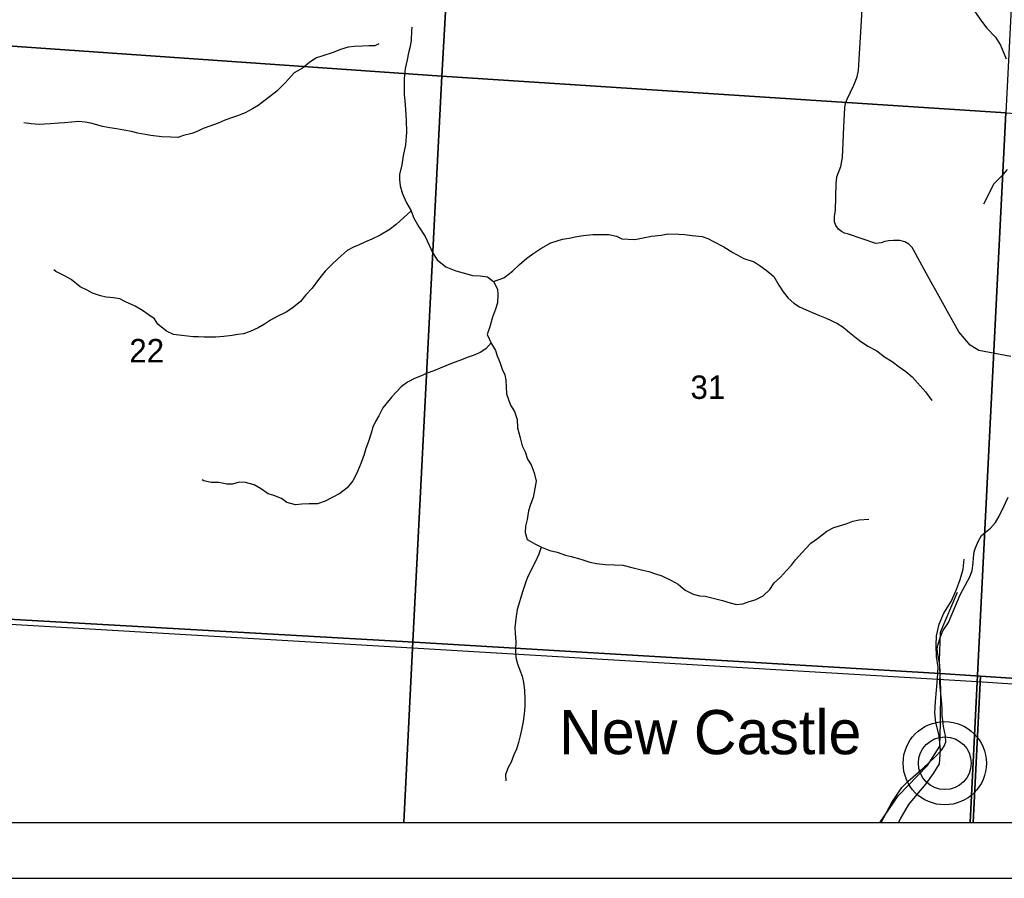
# Model space of a CAD drawing. Extents: x 0 to 44, y -23.8 to 22.
# Drawn here: x 5.562 to 7.321, y 14 to 15.535 of the extents above; entities that cross this region are included whole.
import ezdxf

# ---------------------------------------------------------------- set-up
doc = ezdxf.new("R2010")
doc.units = 0
for name, color, linetype in [('Default', 7, 'Continuous'), ('GM_X_Minor_River', 7, 'Continuous'), ('GM_X_Rail_Line', 7, 'Continuous'), ('GM_X_Section', 7, 'Continuous'), ('GM_X_Section_Text', 7, 'Continuous'), ('GM_X_State_Route', 7, 'Continuous'), ('GM_X_Unincorporated', 7, 'Continuous'), ('GM_X_Unincorporated_Location', 7, 'Continuous'), ('GM_X_Unincorporated_Text', 7, 'Continuous'), ('SH_Cut_Line', 7, 'Continuous'), ('SH_Data', 7, 'Continuous')]:
    doc.layers.add(name, color=color, linetype=linetype)

msp = doc.modelspace()

# ---------------------------------------------------------------- linework, layer by layer
at = {"layer": 'Default'}
msp.add_lwpolyline([(4.1422, 16.6361), (4.3476, 16.1408), (4.5387, 15.7097), (4.856, 14.9939), (4.4538, 14.8144), (4.3443, 14.7655), (3.8639, 14.5533), (4.2071, 14.5278), (4.3437, 14.5311), (4.4919, 14.5227), (6.267, 14.4223), (7.2065, 14.3659), (7.2787, 14.3616), (7.5613, 14.343)], dxfattribs=at)
for points in [[(2.838, 14.1), (7.2659, 14.1), (7.2787, 14.3616), (7.2065, 14.3659), (6.267, 14.4223), (4.4919, 14.5227), (4.3437, 14.5311), (4.2071, 14.5278), (3.8639, 14.5533), (3.0317, 14.1856)], [(5.2407, 14.1), (6.2484, 14.1), (6.2643, 14.4116), (5.2616, 14.4705)], [(6.2484, 14.1), (7.2605, 14.1), (7.2726, 14.3512), (6.2643, 14.4116)], [(7.2659, 14.1), (8.9, 14.1), (8.9, 14.2547), (8.4778, 14.2825), (8.045, 14.3111), (7.5613, 14.343), (7.2787, 14.3616)], [(7.2605, 14.1), (8.2666, 14.1), (8.2829, 14.2852), (7.2726, 14.3512)]]:
    msp.add_lwpolyline(points, close=True, dxfattribs=at)
at = {"layer": 'GM_X_Minor_River'}
for points in [[(7.2686, 15.5494), (7.2791, 15.5343), (7.2901, 15.5195), (7.3056, 15.5036), (7.3147, 15.4891), (7.3249, 15.4649)], [(6.2627, 15.5213), (6.2623, 15.5148), (6.2615, 15.4981), (6.2596, 15.4871), (6.2566, 15.4753), (6.2543, 15.4628), (6.2509, 15.4473), (6.2494, 15.4294), (6.249, 15.4173), (6.2494, 15.4006), (6.2502, 15.3896), (6.2513, 15.3741), (6.2528, 15.3547), (6.2536, 15.3335), (6.2517, 15.3111), (6.2475, 15.2914), (6.2449, 15.2755), (6.2407, 15.258), (6.2407, 15.2485), (6.2418, 15.2379), (6.246, 15.2235), (6.2535, 15.2076), (6.2615, 15.1928), (6.266, 15.181), (6.2755, 15.1647), (6.2864, 15.1469), (6.2936, 15.1317), (6.2996, 15.1185), (6.3083, 15.1052), (6.3234, 15.0927), (6.3412, 15.0859), (6.3609, 15.0806), (6.3711, 15.0772), (6.3851, 15.0768), (6.3983, 15.0753), (6.4089, 15.0669), (6.4157, 15.0533), (6.4164, 15.0434), (6.4157, 15.0286), (6.4123, 15.0173), (6.407, 15.0029), (6.4017, 14.9839), (6.3975, 14.9721), (6.4054, 14.9554), (6.4122, 14.9433), (6.4153, 14.9338), (6.4202, 14.9228), (6.4243, 14.9099), (6.4289, 14.9001), (6.4308, 14.8902), (6.4311, 14.8785), (6.4319, 14.866), (6.4353, 14.8561), (6.4394, 14.8455), (6.4462, 14.8341), (6.4508, 14.8201), (6.4519, 14.8053), (6.4561, 14.7875), (6.4598, 14.7731), (6.4655, 14.7624), (6.4693, 14.7492), (6.4761, 14.7393), (6.4814, 14.7245), (6.4852, 14.7101), (6.4817, 14.69), (6.4795, 14.6805), (6.4749, 14.6684), (6.4715, 14.657), (6.4689, 14.6411), (6.4659, 14.6297), (6.4655, 14.6179), (6.4689, 14.6058), (6.484, 14.5975), (6.4946, 14.5918), (6.5093, 14.5861), (6.5222, 14.5827), (6.5373, 14.5778), (6.5475, 14.5751), (6.5645, 14.5702), (6.5808, 14.5649), (6.5936, 14.5626), (6.608, 14.5611), (6.6246, 14.5604), (6.6397, 14.5596), (6.656, 14.5558), (6.6756, 14.5509), (6.6862, 14.5486), (6.6979, 14.5445), (6.7097, 14.5407), (6.7255, 14.5331), (6.7388, 14.5255), (6.7512, 14.5153), (6.7656, 14.5081), (6.7769, 14.5051), (6.7871, 14.5043), (6.8011, 14.5009), (6.8178, 14.4964), (6.8314, 14.4926), (6.8431, 14.4892), (6.8544, 14.4907)], [(6.2037, 15.4916), (6.1969, 15.4882), (6.1863, 15.4878), (6.175, 15.4874), (6.1606, 15.4866), (6.1493, 15.4855), (6.1357, 15.4813), (6.1224, 15.476), (6.1039, 15.4699), (6.0926, 15.4665), (6.0805, 15.4589), (6.0676, 15.4483), (6.0525, 15.44), (6.037, 15.4225), (6.0215, 15.4069), (6.0086, 15.3967), (5.9882, 15.3815), (5.9784, 15.3751), (5.9648, 15.3682), (5.9512, 15.3629), (5.9391, 15.3587), (5.9274, 15.3546), (5.9168, 15.3496), (5.9017, 15.3447), (5.8903, 15.3401), (5.8805, 15.3356), (5.8699, 15.3314), (5.8552, 15.328), (5.8446, 15.3242), (5.8325, 15.3246), (5.8162, 15.3253), (5.7966, 15.328), (5.7867, 15.3298), (5.7735, 15.3321), (5.7618, 15.3348), (5.7486, 15.3374), (5.7353, 15.3397), (5.7232, 15.3412), (5.7104, 15.3438), (5.7002, 15.3469), (5.6896, 15.3495), (5.6794, 15.3514), (5.6681, 15.3525), (5.6548, 15.3514), (5.6423, 15.3506), (5.6321, 15.3495), (5.617, 15.3483), (5.6068, 15.348), (5.597, 15.3476), (5.583, 15.3483), (5.5698, 15.3506)], [(7.3263, 15.2669), (7.3165, 15.2551), (7.3029, 15.2415), (7.284, 15.2052)], [(6.2615, 15.1928), (6.235, 15.1685), (6.2225, 15.1594), (6.2063, 15.1495), (6.1912, 15.1423), (6.1798, 15.1378), (6.1689, 15.1324), (6.1586, 15.1279), (6.1473, 15.1222), (6.1367, 15.1127), (6.122, 15.0987), (6.108, 15.0854), (6.0959, 15.0702), (6.0845, 15.055), (6.0732, 15.0429), (6.0637, 15.0311), (6.0486, 15.0186), (6.0384, 15.0118), (6.0222, 15.0042), (6.0104, 14.9974), (5.9995, 14.9905), (5.9881, 14.9837), (5.9738, 14.9776), (5.9624, 14.9734), (5.9518, 14.9723), (5.942, 14.9704), (5.9269, 14.9685), (5.9125, 14.9674), (5.9027, 14.967), (5.8917, 14.9673), (5.8819, 14.9681), (5.8721, 14.9677), (5.8517, 14.97), (5.8373, 14.9722), (5.8248, 14.9779), (5.8093, 14.9904), (5.8033, 15.0003), (5.792, 15.0079), (5.7818, 15.0151), (5.7685, 15.0227), (5.7511, 15.0302), (5.7413, 15.0355), (5.73, 15.0374), (5.7167, 15.0386), (5.7069, 15.0412), (5.6926, 15.0458), (5.6827, 15.0514), (5.6703, 15.0571), (5.6544, 15.0704), (5.6434, 15.0764), (5.6268, 15.0844), (5.623, 15.0878)], [(6.4089, 15.0669), (6.427, 15.0734), (6.4425, 15.0852), (6.4554, 15.0973), (6.4686, 15.1083), (6.4811, 15.1174), (6.4936, 15.1258), (6.5113, 15.136), (6.5321, 15.1425), (6.5438, 15.144), (6.5578, 15.147), (6.5695, 15.1489), (6.5862, 15.1505), (6.6149, 15.1505), (6.6285, 15.1475), (6.6383, 15.1429), (6.6614, 15.1418), (6.6731, 15.1441), (6.6909, 15.1479), (6.7083, 15.1498), (6.7204, 15.1517), (6.7396, 15.1513), (6.7502, 15.1505), (6.7635, 15.149), (6.7816, 15.1472), (6.7918, 15.1434), (6.8016, 15.1381), (6.8205, 15.129), (6.8364, 15.1184), (6.8557, 15.1081), (6.8746, 15.1017), (6.8852, 15.0945), (6.8961, 15.0869), (6.9093, 15.0755), (6.9188, 15.06), (6.9264, 15.0482), (6.935, 15.0369), (6.9452, 15.0278), (6.9555, 15.0217), (6.9728, 15.0138), (6.9883, 15.0073), (7.0031, 15.0013), (7.0224, 14.9925), (7.0337, 14.9853), (7.0447, 14.9755), (7.0628, 14.9615), (7.0775, 14.9512), (7.0938, 14.9429), (7.1074, 14.9323), (7.121, 14.9236), (7.1335, 14.9141), (7.1452, 14.9058), (7.1569, 14.8963), (7.1709, 14.88), (7.1803, 14.8694), (7.1917, 14.8542)], [(6.4047, 14.957), (6.3949, 14.9463), (6.385, 14.9399), (6.3726, 14.9346), (6.362, 14.9308), (6.3487, 14.9255), (6.3366, 14.9213), (6.3234, 14.916), (6.3136, 14.9118), (6.3022, 14.9069), (6.2905, 14.9027), (6.2784, 14.8977), (6.2678, 14.8936), (6.255, 14.8867), (6.244, 14.8784), (6.227, 14.8606), (6.2111, 14.8408), (6.2036, 14.8268), (6.1979, 14.8165), (6.1934, 14.8063), (6.19, 14.7957), (6.1854, 14.7809), (6.1809, 14.7684), (6.1771, 14.7559), (6.1707, 14.7384), (6.1639, 14.7229), (6.1574, 14.7103), (6.1476, 14.6978), (6.1344, 14.6879), (6.1208, 14.6807), (6.1079, 14.6743), (6.0943, 14.6693), (6.0792, 14.6693), (6.0663, 14.6686), (6.055, 14.6674), (6.0395, 14.672), (6.0297, 14.6788), (6.0164, 14.6845), (6.0062, 14.6875), (5.9922, 14.6966), (5.9813, 14.7034), (5.9654, 14.7076), (5.9544, 14.708), (5.9423, 14.7045), (5.9325, 14.7045), (5.9178, 14.7072), (5.9045, 14.7076), (5.8913, 14.7102), (5.8881, 14.7122)], [(6.8544, 14.4907), (6.8654, 14.4949), (6.8763, 14.4979), (6.8907, 14.5051), (6.9024, 14.5165), (6.91, 14.5279), (6.9213, 14.5385), (6.9323, 14.5499), (6.941, 14.5598), (6.9482, 14.5692), (6.9659, 14.589), (6.9754, 14.5988), (6.9879, 14.6076), (7.0045, 14.6208), (7.017, 14.6273), (7.0268, 14.63), (7.0389, 14.6338), (7.0506, 14.6383), (7.062, 14.641), (7.0794, 14.6421)], [(6.4946, 14.5918), (6.4934, 14.5903), (6.4897, 14.5796), (6.4829, 14.5652), (6.4708, 14.5409), (6.4673, 14.5315), (6.4609, 14.5136), (6.4511, 14.4803), (6.4484, 14.4639), (6.4469, 14.4476), (6.4473, 14.4382), (6.4484, 14.4226), (6.448, 14.4089), (6.4484, 14.3949), (6.4514, 14.3835), (6.456, 14.3718), (6.4598, 14.3612), (6.4624, 14.3498), (6.4643, 14.3365), (6.465, 14.3202), (6.4647, 14.3088), (6.4643, 14.299), (6.462, 14.28), (6.4586, 14.2652), (6.4563, 14.2546), (6.4533, 14.2428), (6.4499, 14.2311), (6.445, 14.2208), (6.4401, 14.2079), (6.4348, 14.1981), (6.4299, 14.1855), (6.431, 14.1742)], [(7.1325, 14.1), (7.136, 14.1061), (7.1508, 14.132), (7.1649, 14.1491), (7.1819, 14.1688), (7.1949, 14.1874), (7.2055, 14.2049), (7.2071, 14.2289), (7.2052, 14.2555), (7.1992, 14.2783), (7.1974, 14.2958), (7.1986, 14.316), (7.2005, 14.3365), (7.2021, 14.3574), (7.2033, 14.3772), (7.2003, 14.3966), (7.1999, 14.416), (7.2004, 14.4335), (7.2049, 14.454), (7.2133, 14.4742), (7.2262, 14.4947), (7.2361, 14.5164), (7.2426, 14.5339), (7.2476, 14.5525), (7.2499, 14.5704)]]:
    msp.add_lwpolyline(points, dxfattribs=at)
at = {"layer": 'GM_X_Rail_Line'}
msp.add_lwpolyline([(7.0995, 14.1), (7.0995, 14.1001), (7.1316, 14.1477), (7.1843, 14.2017), (7.2062, 14.2365), (7.2072, 14.2781), (7.2079, 14.3379), (7.2053, 14.3885), (7.2071, 14.44), (7.2375, 14.5112)], dxfattribs=at)
at = {"layer": 'GM_X_Section'}
for points in [[(5.3718, 16.5024), (6.3745, 16.447), (6.3163, 15.4337), (5.3182, 15.5035)], [(6.3745, 16.447), (7.376, 16.3855), (7.3239, 15.368), (6.3163, 15.4337)], [(6.3163, 15.4337), (6.2643, 14.4116), (5.2616, 14.4705), (5.3182, 15.5035)], [(7.3239, 15.368), (7.2726, 14.3512), (6.2643, 14.4116), (6.3163, 15.4337)], [(8.3369, 15.3004), (8.2829, 14.2852), (7.2726, 14.3512), (7.3239, 15.368)]]:
    msp.add_lwpolyline(points, close=True, dxfattribs=at)
at = {"layer": 'GM_X_State_Route'}
for points in [[(7.3328, 14.9327), (7.2757, 14.9436), (7.2602, 14.9531), (7.2401, 14.9766), (7.1815, 15.0815), (7.159, 15.1231), (7.157, 15.1274), (7.1506, 15.1334), (7.1439, 15.1376), (7.1346, 15.14), (7.1233, 15.14), (7.1146, 15.1396), (7.1081, 15.1384), (7.1012, 15.1358), (7.0917, 15.1346), (7.043, 15.1512), (7.0356, 15.1533), (7.0305, 15.156), (7.0252, 15.1604), (7.0206, 15.1669), (7.0182, 15.1737), (7.0182, 15.1832), (7.02, 15.1942), (7.0207, 15.2411), (7.022, 15.254), (7.0293, 15.2724), (7.0321, 15.2884), (7.0332, 15.315), (7.0349, 15.3435), (7.0363, 15.3774), (7.0377, 15.3852), (7.0407, 15.3924), (7.0523, 15.4178), (7.0584, 15.4326), (7.0607, 15.4441), (7.0699, 15.5926)], [(7.1012, 14.1), (7.1206, 14.1355), (7.1384, 14.1623), (7.1498, 14.1736), (7.1765, 14.197), (7.1975, 14.2166), (7.2099, 14.2297), (7.2147, 14.2372), (7.2167, 14.2441), (7.2164, 14.2544), (7.2128, 14.2716), (7.2105, 14.2919), (7.2101, 14.3038), (7.2094, 14.3189), (7.2074, 14.336), (7.2062, 14.3496), (7.2067, 14.3654), (7.2068, 14.3686), (7.2063, 14.3815), (7.2028, 14.4005), (7.2015, 14.4093), (7.2024, 14.4168), (7.2071, 14.4315), (7.2116, 14.4425), (7.2216, 14.4571), (7.2425, 14.5068), (7.2602, 14.5402), (7.264, 14.5502), (7.266, 14.5633), (7.2662, 14.5727), (7.2676, 14.5833), (7.2699, 14.5909), (7.2752, 14.6034), (7.2809, 14.6126), (7.2879, 14.6187), (7.2969, 14.6261), (7.3059, 14.6357), (7.312, 14.6474), (7.3206, 14.6643), (7.328, 14.6811)]]:
    msp.add_lwpolyline(points, dxfattribs=at)
at = {"layer": 'GM_X_Unincorporated'}
for radius in [0.0744, 0.0472]:
    msp.add_circle((7.215, 14.2057), radius, dxfattribs=at)
at = {"layer": 'GM_X_Unincorporated_Location'}
msp.add_line((7.215, 14.2057), (7.215, 14.2057), dxfattribs=at)
at = {"layer": 'SH_Cut_Line'}
msp.add_lwpolyline([(4.1422, 16.6361), (4.3476, 16.1408), (4.5387, 15.7097), (4.856, 14.9939), (4.4538, 14.8144), (4.3443, 14.7655), (3.8639, 14.5533), (3.0317, 14.1856), (2.838, 14.1), (8.9, 14.1)], dxfattribs=at)
at = {"layer": 'SH_Data'}
for p, q in [((2.1, 14.1), (8.9, 14.1)), ((2, 14), (9, 14))]:
    msp.add_line(p, q, dxfattribs=at)

# ---------------------------------------------------------------- texts
at = {"layer": 'GM_X_Section_Text'}
for s, p in [('22', (5.7581, 14.9222)), ('31', (6.7606, 14.8569))]:
    msp.add_text(s, height=0.04186, rotation=0, dxfattribs=at).set_placement(p)
at = {"layer": 'GM_X_Unincorporated_Text'}
msp.add_text('New Castle', height=0.07898, rotation=0, dxfattribs=at).set_placement((6.526, 14.2218))

doc.saveas('drawing.dxf')
